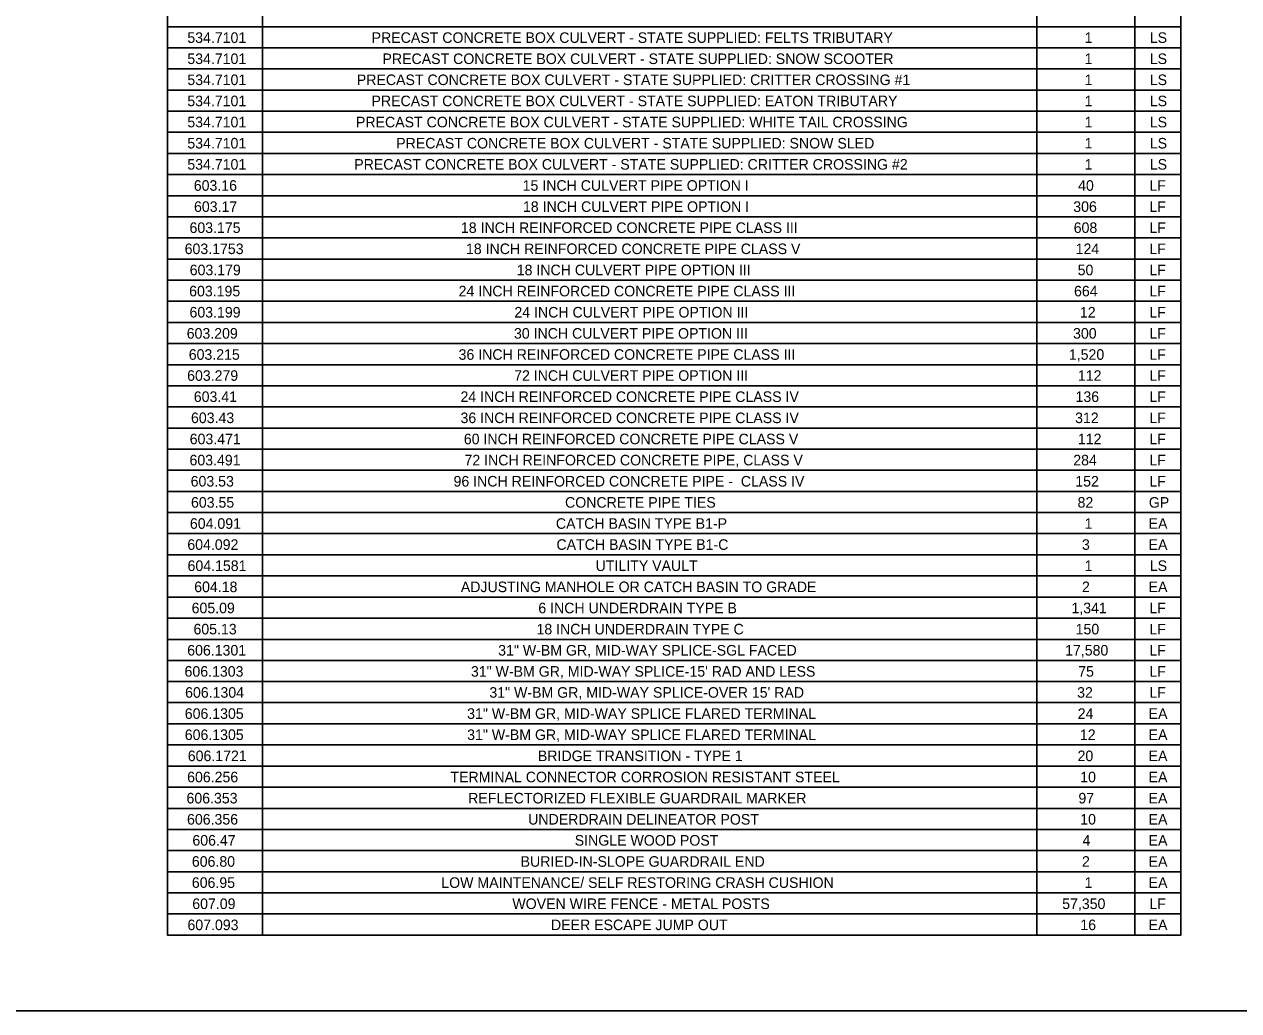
# Model space of a CAD drawing. Extents: x -18.7 to 5.6, y -2.7 to 5.1.
# Drawn here: x -16.637 to -15.505, y 2.172 to 3.091 of the extents above; entities that cross this region are included whole.
import ezdxf

# ---------------------------------------------------------------- set-up
doc = ezdxf.new("R2010")
doc.units = 0
doc.layers.add('ANNOTATION', color=7, linetype='Continuous')
doc.layers.add('BORDER', color=7, linetype='Continuous')

msp = doc.modelspace()

# ---------------------------------------------------------------- linework, layer by layer
at = {"layer": 'ANNOTATION'}
msp.add_lwpolyline([(-17.663, 4.0141), (-13.3075, 4.0141), (-13.3075, 2.1719), (-17.663, 2.1719)], close=True, dxfattribs=at)
at = {"layer": 'BORDER'}
for p, q in [((-16.415, 3.9551), (-16.415, 2.2424)), ((-15.6937, 3.9551), (-15.6937, 2.2424)), ((-15.6023, 3.9551), (-15.6023, 2.2424)), ((-16.5036, 3.0889), (-15.5593, 3.0889)), ((-16.5036, 3.0692), (-15.5593, 3.0692)), ((-16.5036, 3.0495), (-15.5593, 3.0495)), ((-16.5036, 3.0299), (-15.5593, 3.0299)), ((-16.5036, 3.0102), (-15.5593, 3.0102)), ((-16.5036, 2.9905), (-15.5593, 2.9905)), ((-16.5036, 2.9708), (-15.5593, 2.9708)), ((-16.5036, 2.9511), (-15.5593, 2.9511)), ((-16.5036, 2.9314), (-15.5593, 2.9314)), ((-16.5036, 2.9117), (-15.5593, 2.9117)), ((-16.5036, 2.8921), (-15.5593, 2.8921)), ((-16.5036, 2.8724), (-15.5593, 2.8724)), ((-16.5036, 2.8527), (-15.5593, 2.8527)), ((-16.5036, 2.833), (-15.5593, 2.833)), ((-16.5036, 2.8133), (-15.5593, 2.8133)), ((-16.5036, 2.7936), (-15.5593, 2.7936)), ((-16.5036, 2.7739), (-15.5593, 2.7739)), ((-16.5036, 2.7543), (-15.5593, 2.7543)), ((-16.5036, 2.7346), (-15.5593, 2.7346)), ((-16.5036, 2.7149), (-15.5593, 2.7149)), ((-16.5036, 2.6952), (-15.5593, 2.6952)), ((-16.5036, 2.6755), (-15.5593, 2.6755)), ((-16.5036, 2.6558), (-15.5593, 2.6558)), ((-16.5036, 2.6361), (-15.5593, 2.6361)), ((-16.5036, 2.6165), (-15.5593, 2.6165)), ((-16.5036, 2.5968), (-15.5593, 2.5968)), ((-16.5036, 2.5771), (-15.5593, 2.5771)), ((-16.5036, 2.5574), (-15.5593, 2.5574)), ((-16.5036, 2.5377), (-15.5593, 2.5377)), ((-16.5036, 2.518), (-15.5593, 2.518)), ((-16.5036, 2.4983), (-15.5593, 2.4983)), ((-16.5036, 2.4787), (-15.5593, 2.4787)), ((-16.5036, 2.459), (-15.5593, 2.459)), ((-16.5036, 2.4393), (-15.5593, 2.4393)), ((-16.5036, 2.4196), (-15.5593, 2.4196)), ((-16.5036, 2.3999), (-15.5593, 2.3999)), ((-16.5036, 2.3802), (-15.5593, 2.3802)), ((-16.5036, 2.3605), (-15.5593, 2.3605)), ((-16.5036, 2.3408), (-15.5593, 2.3408)), ((-16.5036, 2.3212), (-15.5593, 2.3212)), ((-16.5036, 2.3015), (-15.5593, 2.3015)), ((-16.5036, 2.2818), (-15.5593, 2.2818)), ((-16.5036, 2.2621), (-15.5593, 2.2621)), ((-16.5036, 2.2424), (-15.5593, 2.2424))]:
    msp.add_line(p, q, dxfattribs=at)
msp.add_lwpolyline([(-16.5036, 3.9748), (-15.5593, 3.9748), (-15.5593, 2.2424), (-16.5036, 2.2424)], close=True, dxfattribs=at)

# ---------------------------------------------------------------- texts
at = {"layer": 'ANNOTATION'}
for s, height, p in [('534.7101', 0.00984, (-16.485, 3.0738)), ('PRECAST CONCRETE BOX CULVERT - STATE SUPPLIED: FELTS TRIBUTARY', 0.009843, (-16.3133, 3.0738)), ('1', 0.00984, (-15.649, 3.0738)), ('LS', 0.00984, (-15.5883, 3.0738)), ('534.7101', 0.00984, (-16.485, 3.0541)), ('PRECAST CONCRETE BOX CULVERT - STATE SUPPLIED: SNOW SCOOTER', 0.009843, (-16.3032, 3.0541)), ('1', 0.00984, (-15.649, 3.0541)), ('LS', 0.00984, (-15.5883, 3.0541)), ('534.7101', 0.00984, (-16.485, 3.0345)), ('PRECAST CONCRETE BOX CULVERT - STATE SUPPLIED: CRITTER CROSSING #1', 0.009843, (-16.3271, 3.0345)), ('1', 0.00984, (-15.649, 3.0345)), ('LS', 0.00984, (-15.5883, 3.0345)), ('534.7101', 0.00984, (-16.485, 3.0148)), ('PRECAST CONCRETE BOX CULVERT - STATE SUPPLIED: EATON TRIBUTARY', 0.009843, (-16.3134, 3.0148)), ('1', 0.00984, (-15.649, 3.0148)), ('LS', 0.00984, (-15.5883, 3.0148)), ('534.7101', 0.00984, (-16.485, 2.9951)), ('PRECAST CONCRETE BOX CULVERT - STATE SUPPLIED: WHITE TAIL CROSSING', 0.009843, (-16.3279, 2.9951)), ('1', 0.00984, (-15.649, 2.9951)), ('LS', 0.00984, (-15.5883, 2.9951)), ('534.7101', 0.00984, (-16.485, 2.9754)), ('PRECAST CONCRETE BOX CULVERT - STATE SUPPLIED: SNOW SLED', 0.009843, (-16.2904, 2.9754)), ('1', 0.00984, (-15.649, 2.9754)), ('LS', 0.00984, (-15.5883, 2.9754)), ('534.7101', 0.00984, (-16.485, 2.9557)), ('PRECAST CONCRETE BOX CULVERT - STATE SUPPLIED: CRITTER CROSSING #2', 0.009843, (-16.3295, 2.9557)), ('1', 0.00984, (-15.649, 2.9557)), ('LS', 0.00984, (-15.5883, 2.9557)), ('603.16', 0.00984, (-16.479, 2.936)), ('15 INCH CULVERT PIPE OPTION I', 0.009843, (-16.1726, 2.936)), ('40', 0.00984, (-15.6551, 2.936)), ('LF', 0.00984, (-15.5887, 2.936)), ('603.17', 0.00984, (-16.4788, 2.9163)), ('18 INCH CULVERT PIPE OPTION I', 0.009843, (-16.1723, 2.9163)), ('306', 0.00984, (-15.6596, 2.9163)), ('LF', 0.00984, (-15.5887, 2.9163)), ('603.175', 0.00984, (-16.483, 2.8967)), ('18 INCH REINFORCED CONCRETE PIPE CLASS III', 0.009843, (-16.2301, 2.8967)), ('608', 0.00984, (-15.6592, 2.8967)), ('LF', 0.00984, (-15.5887, 2.8967)), ('603.1753', 0.00984, (-16.4875, 2.877)), ('18 INCH REINFORCED CONCRETE PIPE CLASS V', 0.009843, (-16.2254, 2.877)), ('124', 0.00984, (-15.6574, 2.877)), ('LF', 0.00984, (-15.5887, 2.877)), ('603.179', 0.00984, (-16.4828, 2.8573)), ('18 INCH CULVERT PIPE OPTION III', 0.009843, (-16.1781, 2.8573)), ('50', 0.00984, (-15.6555, 2.8573)), ('LF', 0.00984, (-15.5887, 2.8573)), ('603.195', 0.00984, (-16.4833, 2.8376)), ('24 INCH REINFORCED CONCRETE PIPE CLASS III', 0.009843, (-16.2323, 2.8376)), ('664', 0.00984, (-15.6589, 2.8376)), ('LF', 0.00984, (-15.5887, 2.8376)), ('603.199', 0.00984, (-16.483, 2.8179)), ('24 INCH CULVERT PIPE OPTION III', 0.009843, (-16.1803, 2.8179)), ('12', 0.00984, (-15.6534, 2.8179)), ('LF', 0.00984, (-15.5887, 2.8179)), ('603.209', 0.00984, (-16.4856, 2.7982)), ('30 INCH CULVERT PIPE OPTION III', 0.009843, (-16.1807, 2.7982)), ('300', 0.00984, (-15.6598, 2.7982)), ('LF', 0.00984, (-15.5887, 2.7982)), ('603.215', 0.00984, (-16.4837, 2.7785)), ('36 INCH REINFORCED CONCRETE PIPE CLASS III', 0.009843, (-16.2323, 2.7785)), ('1,520', 0.00984, (-15.6637, 2.7785)), ('LF', 0.00984, (-15.5887, 2.7785)), ('603.279', 0.00984, (-16.4852, 2.7589)), ('72 INCH CULVERT PIPE OPTION III', 0.009843, (-16.1805, 2.7589)), ('112', 0.00984, (-15.6553, 2.7589)), ('LF', 0.00984, (-15.5887, 2.7589)), ('603.41', 0.00984, (-16.479, 2.7392)), ('24 INCH REINFORCED CONCRETE PIPE CLASS IV', 0.009843, (-16.2305, 2.7392)), ('136', 0.00984, (-15.6575, 2.7392)), ('LF', 0.00984, (-15.5887, 2.7392)), ('603.43', 0.00984, (-16.4816, 2.7195)), ('36 INCH REINFORCED CONCRETE PIPE CLASS IV', 0.009843, (-16.2305, 2.7195)), ('312', 0.00984, (-15.6579, 2.7195)), ('LF', 0.00984, (-15.5887, 2.7195)), ('603.471', 0.00984, (-16.4828, 2.6998)), ('60 INCH REINFORCED CONCRETE PIPE CLASS V', 0.009843, (-16.2274, 2.6998)), ('112', 0.00984, (-15.6553, 2.6998)), ('LF', 0.00984, (-15.5887, 2.6998)), ('603.491', 0.00984, (-16.483, 2.6801)), ('72 INCH REINFORCED CONCRETE PIPE, CLASS V', 0.009843, (-16.2268, 2.6801)), ('284', 0.00984, (-15.6596, 2.6801)), ('LF', 0.00984, (-15.5887, 2.6801)), ('603.53', 0.00984, (-16.4819, 2.6604)), ('96 INCH REINFORCED CONCRETE PIPE -  CLASS IV', 0.009843, (-16.237, 2.6604)), ('152', 0.00984, (-15.6577, 2.6604)), ('LF', 0.00984, (-15.5887, 2.6604)), ('603.55', 0.00984, (-16.4816, 2.6407)), ('CONCRETE PIPE TIES', 0.009843, (-16.1331, 2.6407)), ('82', 0.00984, (-15.6556, 2.6407)), ('GP', 0.00984, (-15.5892, 2.6407)), ('604.091', 0.00984, (-16.4826, 2.621)), ('CATCH BASIN TYPE B1-P', 0.009843, (-16.1416, 2.621)), ('1', 0.00984, (-15.649, 2.621)), ('EA', 0.00984, (-15.5894, 2.621)), ('604.092', 0.00984, (-16.485, 2.6014)), ('CATCH BASIN TYPE B1-C', 0.009843, (-16.1411, 2.6014)), ('3', 0.00984, (-15.6515, 2.6014)), ('EA', 0.00984, (-15.5894, 2.6014)), ('604.1581', 0.00984, (-16.4848, 2.5817)), ('UTILITY VAULT', 0.009843, (-16.1046, 2.5817)), ('1', 0.00984, (-15.649, 2.5817)), ('LS', 0.00984, (-15.5883, 2.5817)), ('604.18', 0.00984, (-16.4786, 2.562)), ('ADJUSTING MANHOLE OR CATCH BASIN TO GRADE', 0.009843, (-16.2302, 2.562)), ('2', 0.00984, (-15.6515, 2.562)), ('EA', 0.00984, (-15.5894, 2.562)), ('605.09', 0.00984, (-16.481, 2.5423)), ('6 INCH UNDERDRAIN TYPE B', 0.009843, (-16.158, 2.5423)), ('1,341', 0.00984, (-15.6613, 2.5423)), ('LF', 0.00984, (-15.5887, 2.5423)), ('605.13', 0.00984, (-16.4793, 2.5226)), ('18 INCH UNDERDRAIN TYPE C', 0.009843, (-16.1597, 2.5226)), ('150', 0.00984, (-15.6574, 2.5226)), ('LF', 0.00984, (-15.5887, 2.5226)), ('606.1301', 0.00984, (-16.4851, 2.5029)), ('31" W-BM GR, MID-WAY SPLICE-SGL FACED', 0.009843, (-16.1954, 2.5029)), ('17,580', 0.00984, (-15.6672, 2.5029)), ('LF', 0.00984, (-15.5887, 2.5029)), ('606.1303', 0.00984, (-16.4876, 2.4832)), ('31" W-BM GR, MID-WAY SPLICE-15\' RAD AND LESS', 0.009843, (-16.2208, 2.4832)), ('75', 0.00984, (-15.655, 2.4832)), ('LF', 0.00984, (-15.5887, 2.4832)), ('606.1304', 0.00984, (-16.4871, 2.4636)), ('31" W-BM GR, MID-WAY SPLICE-OVER 15\' RAD', 0.009843, (-16.2036, 2.4636)), ('32', 0.00984, (-15.656, 2.4636)), ('LF', 0.00984, (-15.5887, 2.4636)), ('606.1305', 0.00984, (-16.4874, 2.4439)), ('31" W-BM GR, MID-WAY SPLICE FLARED TERMINAL', 0.009843, (-16.2243, 2.4439)), ('24', 0.00984, (-15.6555, 2.4439)), ('EA', 0.00984, (-15.5894, 2.4439)), ('606.1305', 0.00984, (-16.4874, 2.4242)), ('31" W-BM GR, MID-WAY SPLICE FLARED TERMINAL', 0.009843, (-16.2243, 2.4242)), ('12', 0.00984, (-15.6534, 2.4242)), ('EA', 0.00984, (-15.5894, 2.4242)), ('606.1721', 0.00984, (-16.4846, 2.4045)), ('BRIDGE TRANSITION - TYPE 1', 0.009843, (-16.1584, 2.4045)), ('20', 0.00984, (-15.6556, 2.4045)), ('EA', 0.00984, (-15.5894, 2.4045)), ('606.256', 0.00984, (-16.4852, 2.3848)), ('TERMINAL CONNECTOR CORROSION RESISTANT STEEL', 0.009843, (-16.2399, 2.3848)), ('10', 0.00984, (-15.6531, 2.3848)), ('EA', 0.00984, (-15.5894, 2.3848)), ('606.353', 0.00984, (-16.4858, 2.3651)), ('REFLECTORIZED FLEXIBLE GUARDRAIL MARKER', 0.009843, (-16.2234, 2.3651)), ('97', 0.00984, (-15.6548, 2.3651)), ('EA', 0.00984, (-15.5894, 2.3651)), ('606.356', 0.00984, (-16.4853, 2.3454)), ('UNDERDRAIN DELINEATOR POST', 0.009843, (-16.1675, 2.3454)), ('10', 0.00984, (-15.6531, 2.3454)), ('EA', 0.00984, (-15.5894, 2.3454)), ('606.47', 0.00984, (-16.4803, 2.3258)), ('SINGLE WOOD POST', 0.009843, (-16.1241, 2.3258)), ('4', 0.00984, (-15.651, 2.3258)), ('EA', 0.00984, (-15.5894, 2.3258)), ('606.80', 0.00984, (-16.4808, 2.3061)), ('BURIED-IN-SLOPE GUARDRAIL END', 0.009843, (-16.1745, 2.3061)), ('2', 0.00984, (-15.6515, 2.3061)), ('EA', 0.00984, (-15.5894, 2.3061)), ('606.95', 0.00984, (-16.4808, 2.2864)), ('LOW MAINTENANCE/ SELF RESTORING CRASH CUSHION', 0.009843, (-16.2484, 2.2864)), ('1', 0.00984, (-15.649, 2.2864)), ('EA', 0.00984, (-15.5894, 2.2864)), ('607.09', 0.00984, (-16.4804, 2.2667)), ('WOVEN WIRE FENCE - METAL POSTS', 0.009843, (-16.1822, 2.2667)), ('57,350', 0.00984, (-15.6699, 2.2667)), ('LF', 0.00984, (-15.5887, 2.2667)), ('607.093', 0.00984, (-16.4849, 2.247)), ('DEER ESCAPE JUMP OUT', 0.009843, (-16.1462, 2.247)), ('16', 0.00984, (-15.653, 2.247)), ('EA', 0.00984, (-15.5894, 2.247))]:
    msp.add_text(s, height=height, dxfattribs=at).set_placement(p)

doc.saveas('drawing.dxf')
